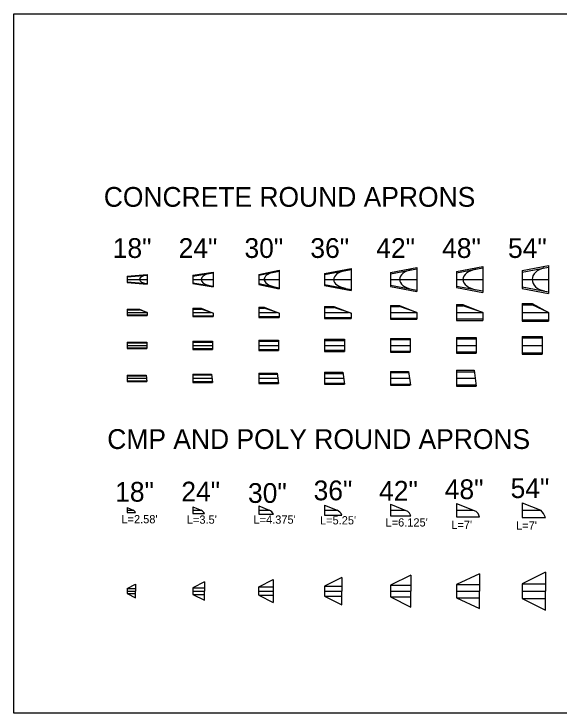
# Model space of a CAD drawing. Extents: x 20500915 to 20506562, y 7965868 to 7970770.
# Drawn here: x 20500915.2 to 20501080.6, y 7966058.6 to 7966270.8 of the extents above; entities that cross this region are included whole.
import ezdxf

# ---------------------------------------------------------------- set-up
doc = ezdxf.new("R2010")
doc.units = 0
doc.layers.add('brgPreStructureNew', color=7, linetype='Continuous')

msp = doc.modelspace()

# ---------------------------------------------------------------- linework, layer by layer
at = {"layer": 'brgPreStructureNew'}
for p, q in [((20500989.49, 7966191.78), (20500995.64, 7966193.03)), ((20500989.49, 7966191.48), (20500995.64, 7966192.73)), ((20500995.64, 7966193.03), (20500995.64, 7966187.43)), ((20501009.49, 7966192.07), (20501017.49, 7966193.57)), ((20501009.49, 7966191.73), (20501017.49, 7966193.23)), ((20501017.49, 7966193.57), (20501017.49, 7966186.89)), ((20501029.49, 7966192.36), (20501037.49, 7966193.86)), ((20501029.49, 7966191.98), (20501037.49, 7966193.48)), ((20501037.49, 7966193.86), (20501037.49, 7966186.6)), ((20501049.49, 7966192.66), (20501057.49, 7966194.16)), ((20501049.49, 7966192.23), (20501057.49, 7966193.73)), ((20501057.49, 7966194.16), (20501057.49, 7966186.3)), ((20501069.49, 7966192.95), (20501077.49, 7966194.45)), ((20501069.49, 7966192.48), (20501077.49, 7966193.98)), ((20501069.49, 7966192.95), (20501069.49, 7966187.51)), ((20501077.49, 7966194.45), (20501077.49, 7966186.01)), ((20500949.49, 7966191.19), (20500955.57, 7966191.69)), ((20500949.49, 7966190.98), (20500955.57, 7966191.48)), ((20500949.49, 7966191.19), (20500949.49, 7966189.27)), ((20500955.57, 7966191.69), (20500955.57, 7966188.77)), ((20500969.49, 7966191.48), (20500975.61, 7966192.48)), ((20500969.49, 7966191.23), (20500975.61, 7966192.23)), ((20500969.49, 7966191.48), (20500969.49, 7966188.98)), ((20500975.61, 7966192.48), (20500975.61, 7966187.98)), ((20500989.49, 7966191.78), (20500989.49, 7966188.68)), ((20501009.49, 7966192.07), (20501009.49, 7966188.39)), ((20501029.49, 7966192.36), (20501029.49, 7966188.1)), ((20501049.49, 7966192.66), (20501049.49, 7966187.8)), ((20500949.49, 7966190.23), (20500953.32, 7966190.23)), ((20500949.49, 7966189.48), (20500955.57, 7966188.98)), ((20500949.49, 7966189.27), (20500955.57, 7966188.77)), ((20500953.32, 7966190.23), (20500955.57, 7966190.23)), ((20500969.49, 7966190.23), (20500971.99, 7966190.23)), ((20500969.49, 7966189.23), (20500975.61, 7966188.23)), ((20500969.49, 7966188.98), (20500975.61, 7966187.98)), ((20500971.99, 7966190.23), (20500975.61, 7966190.23)), ((20500989.49, 7966190.23), (20500991.14, 7966190.23)), ((20500989.49, 7966188.98), (20500995.64, 7966187.73)), ((20500989.49, 7966188.68), (20500995.64, 7966187.43)), ((20500991.14, 7966190.23), (20500995.64, 7966190.23)), ((20501009.49, 7966190.23), (20501012.24, 7966190.23)), ((20501009.49, 7966188.73), (20501017.49, 7966187.23)), ((20501012.24, 7966190.23), (20501017.49, 7966190.23)), ((20501029.49, 7966190.23), (20501032.24, 7966190.23)), ((20501029.49, 7966188.48), (20501037.49, 7966186.98)), ((20501032.24, 7966190.23), (20501037.49, 7966190.23)), ((20501049.49, 7966190.23), (20501051.49, 7966190.23)), ((20501051.49, 7966190.23), (20501057.49, 7966190.23)), ((20501069.49, 7966190.23), (20501072.49, 7966190.23)), ((20501072.49, 7966190.23), (20501077.49, 7966190.23)), ((20501009.49, 7966188.39), (20501017.49, 7966186.89)), ((20501029.49, 7966188.1), (20501037.49, 7966186.6)), ((20501049.49, 7966188.23), (20501057.49, 7966186.73)), ((20501049.49, 7966187.8), (20501057.49, 7966186.3)), ((20501069.49, 7966187.98), (20501077.49, 7966186.48)), ((20501069.49, 7966187.51), (20501077.49, 7966186.01)), ((20501029.49, 7966182.31), (20501032.24, 7966182.31)), ((20501029.49, 7966182.31), (20501029.49, 7966178.16)), ((20501032.24, 7966182.31), (20501037.49, 7966180.23)), ((20501049.49, 7966182.65), (20501051.49, 7966182.65)), ((20501049.49, 7966182.65), (20501049.49, 7966177.81)), ((20501049.49, 7966182.23), (20501051.49, 7966182.23)), ((20501051.49, 7966182.65), (20501057.49, 7966180.23)), ((20501057.49, 7966180.23), (20501051.49, 7966182.23)), ((20501069.49, 7966182.94), (20501069.49, 7966177.52)), ((20501069.49, 7966182.94), (20501072.49, 7966182.94)), ((20501069.49, 7966182.48), (20501072.49, 7966182.48)), ((20501072.49, 7966182.94), (20501077.49, 7966180.23)), ((20501077.49, 7966180.23), (20501072.49, 7966182.48)), ((20500949.49, 7966181.19), (20500953.32, 7966181.19)), ((20500949.49, 7966181.19), (20500949.49, 7966179.27)), ((20500949.49, 7966180.98), (20500953.32, 7966180.98)), ((20500949.49, 7966180.23), (20500955.57, 7966180.23)), ((20500953.32, 7966181.19), (20500955.57, 7966180.23)), ((20500955.57, 7966180.23), (20500953.32, 7966180.98)), ((20500955.57, 7966180.23), (20500955.57, 7966179.27)), ((20500969.49, 7966181.48), (20500971.99, 7966181.48)), ((20500969.49, 7966181.48), (20500969.49, 7966178.98)), ((20500969.49, 7966181.23), (20500971.99, 7966181.23)), ((20500969.49, 7966180.23), (20500974.98, 7966180.23)), ((20500971.99, 7966181.48), (20500975.61, 7966180.02)), ((20500975.61, 7966180.02), (20500971.99, 7966181.23)), ((20500975.61, 7966180.02), (20500975.61, 7966178.98)), ((20500989.49, 7966181.77), (20500991.14, 7966181.77)), ((20500989.49, 7966181.77), (20500989.49, 7966178.69)), ((20500989.49, 7966181.48), (20500991.14, 7966181.48)), ((20500989.49, 7966180.23), (20500994.89, 7966180.23)), ((20500991.14, 7966181.77), (20500995.64, 7966179.98)), ((20500995.64, 7966179.98), (20500991.14, 7966181.48)), ((20500995.64, 7966179.98), (20500995.64, 7966178.69)), ((20501009.49, 7966182.06), (20501012.24, 7966182.06)), ((20501009.49, 7966182.06), (20501009.49, 7966178.4)), ((20501009.49, 7966181.73), (20501012.24, 7966181.73)), ((20501009.49, 7966180.23), (20501016.74, 7966180.23)), ((20501012.24, 7966182.06), (20501017.49, 7966179.98)), ((20501017.49, 7966179.98), (20501012.24, 7966181.73)), ((20501017.49, 7966179.98), (20501017.49, 7966178.4)), ((20501029.49, 7966181.98), (20501032.24, 7966181.98)), ((20501029.49, 7966180.23), (20501037.49, 7966180.23)), ((20501037.49, 7966180.23), (20501032.24, 7966181.98)), ((20501037.49, 7966180.23), (20501037.49, 7966178.16)), ((20501049.49, 7966180.23), (20501057.49, 7966180.23)), ((20501057.49, 7966180.23), (20501057.49, 7966177.81)), ((20501069.49, 7966180.23), (20501077.49, 7966180.23)), ((20501077.49, 7966180.23), (20501077.49, 7966177.52)), ((20500949.49, 7966179.48), (20500955.57, 7966179.48)), ((20500949.49, 7966179.27), (20500955.57, 7966179.27)), ((20500969.49, 7966179.23), (20500975.61, 7966179.23)), ((20500969.49, 7966178.98), (20500975.61, 7966178.98)), ((20500989.49, 7966178.98), (20500995.64, 7966178.98)), ((20500989.49, 7966178.69), (20500995.64, 7966178.69)), ((20501009.49, 7966178.73), (20501017.49, 7966178.73)), ((20501009.49, 7966178.4), (20501017.49, 7966178.4)), ((20501029.49, 7966178.48), (20501037.49, 7966178.48)), ((20501029.49, 7966178.16), (20501037.49, 7966178.16)), ((20501049.49, 7966178.23), (20501057.49, 7966178.23)), ((20501069.49, 7966177.98), (20501077.49, 7966177.98)), ((20501049.49, 7966177.81), (20501057.49, 7966177.81)), ((20501069.49, 7966177.52), (20501077.49, 7966177.52)), ((20500969.49, 7966171.48), (20500975.49, 7966171.48)), ((20500969.49, 7966171.48), (20500969.49, 7966168.98)), ((20500975.49, 7966171.48), (20500975.49, 7966168.98)), ((20500989.49, 7966171.77), (20500995.49, 7966171.77)), ((20500989.49, 7966171.77), (20500989.49, 7966168.69)), ((20500989.49, 7966171.48), (20500995.49, 7966171.48)), ((20500995.49, 7966171.77), (20500995.49, 7966168.69)), ((20501009.49, 7966172.06), (20501015.49, 7966172.06)), ((20501009.49, 7966172.06), (20501009.49, 7966168.4)), ((20501009.49, 7966171.73), (20501015.49, 7966171.73)), ((20501015.49, 7966172.06), (20501015.49, 7966168.4)), ((20501029.49, 7966172.31), (20501035.49, 7966172.31)), ((20501029.49, 7966172.31), (20501029.49, 7966168.16)), ((20501029.49, 7966171.98), (20501035.49, 7966171.98)), ((20501035.49, 7966172.31), (20501035.49, 7966168.16)), ((20501049.49, 7966172.65), (20501055.49, 7966172.65)), ((20501049.49, 7966172.65), (20501049.49, 7966167.81)), ((20501049.49, 7966172.23), (20501055.49, 7966172.23)), ((20501055.49, 7966172.65), (20501055.49, 7966167.81)), ((20501069.49, 7966172.94), (20501069.49, 7966167.52)), ((20501069.49, 7966172.94), (20501075.49, 7966172.94)), ((20501069.49, 7966172.48), (20501075.49, 7966172.48)), ((20501075.49, 7966172.94), (20501075.49, 7966167.52)), ((20500949.49, 7966171.19), (20500949.49, 7966169.27)), ((20500949.49, 7966171.19), (20500955.49, 7966171.19)), ((20500949.49, 7966170.98), (20500955.49, 7966170.98)), ((20500949.49, 7966170.23), (20500955.49, 7966170.23)), ((20500949.49, 7966169.48), (20500955.49, 7966169.48)), ((20500955.49, 7966171.19), (20500955.49, 7966169.27)), ((20500969.49, 7966171.23), (20500975.49, 7966171.23)), ((20500969.49, 7966170.23), (20500975.49, 7966170.23)), ((20500989.49, 7966170.23), (20500995.49, 7966170.23)), ((20501009.49, 7966170.23), (20501015.49, 7966170.23)), ((20501029.49, 7966170.23), (20501035.49, 7966170.23)), ((20501049.49, 7966170.23), (20501055.49, 7966170.23)), ((20501069.49, 7966170.23), (20501075.49, 7966170.23)), ((20500949.49, 7966169.27), (20500955.49, 7966169.27)), ((20500969.49, 7966169.23), (20500975.49, 7966169.23)), ((20500969.49, 7966168.98), (20500975.49, 7966168.98)), ((20500989.49, 7966168.98), (20500995.49, 7966168.98)), ((20500989.49, 7966168.69), (20500995.49, 7966168.69)), ((20501009.49, 7966168.73), (20501015.49, 7966168.73)), ((20501009.49, 7966168.4), (20501015.49, 7966168.4)), ((20501029.49, 7966168.48), (20501035.49, 7966168.48)), ((20501029.49, 7966168.16), (20501035.49, 7966168.16)), ((20501049.49, 7966168.23), (20501055.49, 7966168.23)), ((20501049.49, 7966167.81), (20501055.49, 7966167.81)), ((20501069.49, 7966167.98), (20501075.49, 7966167.98)), ((20501069.49, 7966167.52), (20501075.49, 7966167.52)), ((20500949.49, 7966161.19), (20500949.49, 7966159.27)), ((20500949.49, 7966161.19), (20500955.26, 7966161.19)), ((20500949.49, 7966160.98), (20500955.29, 7966160.98)), ((20500955.26, 7966161.19), (20500955.52, 7966159.27)), ((20500969.49, 7966161.48), (20500975.16, 7966161.48)), ((20500969.49, 7966161.48), (20500969.49, 7966158.98)), ((20500969.49, 7966161.23), (20500975.19, 7966161.23)), ((20500975.16, 7966161.48), (20500975.49, 7966158.98)), ((20500989.49, 7966161.77), (20500995.08, 7966161.77)), ((20500989.49, 7966161.77), (20500989.49, 7966158.69)), ((20500989.49, 7966161.48), (20500995.12, 7966161.48)), ((20500995.08, 7966161.77), (20500995.49, 7966158.69)), ((20501009.49, 7966162.06), (20501015.01, 7966162.06)), ((20501009.49, 7966162.06), (20501009.49, 7966158.4)), ((20501009.49, 7966161.73), (20501015.05, 7966161.73)), ((20501015.01, 7966162.06), (20501015.49, 7966158.4)), ((20501029.49, 7966162.31), (20501034.98, 7966162.31)), ((20501029.49, 7966162.31), (20501029.49, 7966158.16)), ((20501029.49, 7966161.98), (20501035.03, 7966161.98)), ((20501034.98, 7966162.31), (20501035.53, 7966158.16)), ((20501049.49, 7966162.65), (20501054.85, 7966162.65)), ((20501049.49, 7966162.65), (20501049.49, 7966157.81)), ((20501049.49, 7966162.23), (20501054.91, 7966162.23)), ((20501054.85, 7966162.65), (20501055.49, 7966157.81)), ((20500949.49, 7966160.23), (20500955.39, 7966160.23)), ((20500949.49, 7966159.48), (20500955.49, 7966159.48)), ((20500949.49, 7966159.27), (20500955.49, 7966159.27)), ((20500969.49, 7966160.23), (20500975.32, 7966160.23)), ((20500969.49, 7966159.23), (20500975.45, 7966159.23)), ((20500969.49, 7966158.98), (20500975.49, 7966158.98)), ((20500989.49, 7966160.23), (20500995.28, 7966160.23)), ((20500989.49, 7966158.98), (20500995.45, 7966158.98)), ((20501009.49, 7966160.23), (20501015.25, 7966160.23)), ((20501009.49, 7966158.73), (20501015.44, 7966158.73)), ((20501029.49, 7966160.23), (20501035.26, 7966160.23)), ((20501049.49, 7966160.23), (20501055.17, 7966160.23)), ((20500989.49, 7966158.69), (20500995.49, 7966158.69)), ((20501009.49, 7966158.4), (20501015.49, 7966158.4)), ((20501029.49, 7966158.48), (20501035.49, 7966158.48)), ((20501029.49, 7966158.16), (20501035.49, 7966158.16)), ((20501049.49, 7966158.23), (20501055.43, 7966158.23)), ((20501049.49, 7966157.81), (20501055.49, 7966157.81)), ((20500949.49, 7966120.98), (20500949.49, 7966119.48)), ((20500949.49, 7966120.98), (20500951.36, 7966120.23)), ((20500969.49, 7966121.23), (20500969.49, 7966119.23)), ((20500969.49, 7966121.23), (20500971.99, 7966120.23)), ((20500989.55, 7966121.48), (20500989.55, 7966118.98)), ((20500989.55, 7966121.48), (20500992.65, 7966120.24)), ((20501009.49, 7966121.73), (20501009.49, 7966118.73)), ((20501009.49, 7966121.73), (20501013.29, 7966120.21)), ((20501029.49, 7966121.98), (20501034.63, 7966119.92)), ((20501029.49, 7966121.98), (20501029.49, 7966118.48)), ((20501049.49, 7966122.23), (20501055.4, 7966119.87)), ((20501049.49, 7966122.23), (20501049.49, 7966118.23)), ((20501069.49, 7966122.48), (20501075.11, 7966120.23)), ((20501069.49, 7966122.48), (20501069.49, 7966117.98)), ((20500949.49, 7966120.23), (20500951.36, 7966120.23)), ((20500949.49, 7966119.48), (20500952.07, 7966119.48)), ((20500969.49, 7966120.23), (20500971.99, 7966120.23)), ((20500969.49, 7966119.23), (20500972.99, 7966119.23)), ((20500989.55, 7966120.23), (20500992.67, 7966120.23)), ((20500989.55, 7966118.98), (20500993.92, 7966118.98)), ((20501009.49, 7966120.23), (20501013.24, 7966120.23)), ((20501009.49, 7966118.73), (20501014.74, 7966118.73)), ((20501029.49, 7966120.23), (20501033.86, 7966120.23)), ((20501029.49, 7966118.48), (20501035.61, 7966118.48)), ((20501049.49, 7966120.23), (20501054.68, 7966120.23)), ((20501069.49, 7966120.23), (20501075.11, 7966120.23)), ((20501049.49, 7966118.23), (20501056.49, 7966118.23)), ((20501069.49, 7966117.98), (20501076.49, 7966117.98)), ((20501014.74, 7966099.81), (20501009.49, 7966097.14)), ((20501014.74, 7966099.81), (20501014.74, 7966095.64)), ((20501035.61, 7966100.47), (20501029.49, 7966097.39)), ((20501035.61, 7966100.47), (20501035.61, 7966095.64)), ((20501056.49, 7966100.89), (20501049.49, 7966097.64)), ((20501056.49, 7966100.89), (20501056.49, 7966095.64)), ((20501076.49, 7966101.39), (20501069.49, 7966097.89)), ((20501076.49, 7966101.39), (20501076.49, 7966095.64)), ((20500949.49, 7966096.39), (20500952.07, 7966097.72)), ((20500952.07, 7966097.72), (20500952.07, 7966095.64)), ((20500972.99, 7966098.43), (20500969.49, 7966096.64)), ((20500972.99, 7966098.43), (20500972.99, 7966095.64)), ((20500989.49, 7966096.89), (20500993.86, 7966099.14)), ((20500993.86, 7966099.14), (20500993.86, 7966092.14)), ((20501029.49, 7966097.39), (20501035.61, 7966097.39)), ((20501029.49, 7966097.39), (20501029.49, 7966093.89)), ((20501049.49, 7966097.64), (20501056.49, 7966097.64)), ((20501049.49, 7966097.64), (20501049.49, 7966095.64)), ((20501069.49, 7966097.89), (20501076.49, 7966097.89)), ((20501069.49, 7966097.89), (20501069.49, 7966093.39)), ((20500949.49, 7966096.39), (20500952.07, 7966096.39)), ((20500949.49, 7966096.39), (20500949.49, 7966094.89)), ((20500949.49, 7966095.64), (20500952.07, 7966095.64)), ((20500952.07, 7966093.56), (20500952.07, 7966095.64)), ((20500969.49, 7966096.64), (20500972.99, 7966096.64)), ((20500969.49, 7966096.64), (20500969.49, 7966094.64)), ((20500969.49, 7966095.64), (20500972.99, 7966095.64)), ((20500972.99, 7966092.85), (20500972.99, 7966095.64)), ((20500989.49, 7966096.89), (20500993.86, 7966096.89)), ((20500989.49, 7966094.39), (20500989.49, 7966096.89)), ((20500989.49, 7966095.64), (20500993.86, 7966095.64)), ((20501009.49, 7966097.14), (20501014.74, 7966097.14)), ((20501009.49, 7966097.14), (20501009.49, 7966094.14)), ((20501009.49, 7966095.64), (20501014.74, 7966095.64)), ((20501014.74, 7966091.47), (20501014.74, 7966095.64)), ((20501029.49, 7966095.64), (20501035.61, 7966095.64)), ((20501035.61, 7966090.81), (20501035.61, 7966095.64)), ((20501049.49, 7966095.64), (20501056.49, 7966095.64)), ((20501049.49, 7966095.64), (20501049.49, 7966093.64)), ((20501056.49, 7966090.39), (20501056.49, 7966095.64)), ((20501069.49, 7966095.64), (20501076.49, 7966095.64)), ((20501076.49, 7966089.89), (20501076.49, 7966095.64)), ((20500949.49, 7966094.89), (20500952.07, 7966094.89)), ((20500949.49, 7966094.89), (20500952.07, 7966093.56)), ((20500969.49, 7966094.64), (20500972.99, 7966094.64)), ((20500969.49, 7966094.64), (20500972.99, 7966092.85)), ((20500989.49, 7966094.39), (20500993.86, 7966094.39)), ((20500989.49, 7966094.39), (20500993.86, 7966092.14)), ((20501009.49, 7966094.14), (20501014.74, 7966094.14)), ((20501009.49, 7966094.14), (20501014.74, 7966091.47)), ((20501029.49, 7966093.89), (20501035.61, 7966093.89)), ((20501029.49, 7966093.89), (20501035.61, 7966090.81)), ((20501049.49, 7966093.64), (20501056.49, 7966093.64)), ((20501049.49, 7966093.64), (20501056.49, 7966090.39)), ((20501069.49, 7966093.39), (20501076.49, 7966093.39)), ((20501069.49, 7966093.39), (20501076.49, 7966089.89))]:
    msp.add_line(p, q, dxfattribs=at)
msp.add_lwpolyline([(20500915.17, 7966270.8), (20501554.47, 7966270.8), (20501554.47, 7966058.64), (20500915.17, 7966058.64)], close=True, dxfattribs=at)
for centre, radius, start, end in [((20500950.95, 7966119.14), 1.17, 17.1311, 69.6715), ((20500970.28, 7966117.52), 3.2, 32.2488, 57.7512), ((20500991.75, 7966118.06), 2.36, 23.0367, 67.4986), ((20501011.7, 7966117.21), 3.4, 26.665, 62.1679), ((20501032.53, 7966117.44), 3.26, 18.7213, 49.8517), ((20501053.81, 7966117.63), 2.74, 12.6598, 54.6475), ((20501071.43, 7966116.43), 5.29, 17.0131, 45.9188)]:
    msp.add_arc(centre, radius, start, end, dxfattribs=at)
for centre, major_axis, ratio, start_param, end_param in [((20501017.49, 7966190.23), (5.25, 0), 0.539087, 1.943229, 4.371953), ((20501037.49, 7966190.23), (5.25, 0), 0.589894, 1.887368, 4.39014), ((20501057.49, 7966190.23), (6, 0), 0.552144, 1.909281, 4.380017), ((20501077.49, 7966190.23), (5, 0), 0.725878, 1.858842, 4.441642), ((20500955.57, 7966190.23), (2.25, 0), 0.548754, 1.713763, 4.561434), ((20500975.61, 7966190.23), (3.62, 0), 0.527355, 1.900882, 4.368644), ((20500995.64, 7966190.23), (4.5, 0), 0.516797, 1.967696, 4.372548)]:
    msp.add_ellipse(centre, major_axis=major_axis, ratio=ratio, start_param=start_param, end_param=end_param, dxfattribs=at)

# ---------------------------------------------------------------- texts
for s, height, p in [('CONCRETE ROUND APRONS', 6, (20500942.44, 7966212.29)), ('18"', 6, (20500945.15, 7966196.76)), ('24"', 6, (20500965.15, 7966196.76)), ('30"', 6, (20500985.15, 7966196.76)), ('36"', 6, (20501005.15, 7966196.76)), ('42"', 6, (20501025.15, 7966196.76)), ('48"', 6, (20501045.15, 7966196.76)), ('54"', 6, (20501065.15, 7966196.76)), ('CMP AND POLY ROUND APRONS', 6, (20500943.49, 7966138.78)), ('36"', 6, (20501006.13, 7966123.2)), ('42"', 6, (20501026.02, 7966123.09)), ('48"', 6, (20501045.95, 7966123.55)), ('54"', 6, (20501065.94, 7966123.88)), ('18"', 6, (20500945.89, 7966122.79)), ('24"', 6, (20500965.97, 7966122.84)), ('30"', 6, (20500986.22, 7966122.41)), ("L=2.58'", 2.5, (20500947.8, 7966116.22)), ("L=3.5'", 2.5, (20500967.65, 7966116.09)), ("L=4.375'", 2.5, (20500987.89, 7966116.09)), ("L=5.25'", 2.5, (20501008.08, 7966115.88)), ("L=6.125'", 2.5, (20501027.98, 7966115.24)), ("L=7'", 2.5, (20501047.94, 7966114.51)), ("L=7'", 2.5, (20501067.62, 7966114.3))]:
    msp.add_text(s, height=height, dxfattribs=at).set_placement(p)

doc.saveas('drawing.dxf')
